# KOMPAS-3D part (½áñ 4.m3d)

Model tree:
1. Эскиз:1
2. Операция выдавливания:1
     Расстояние 1 = 20
3. Эскиз:2
4. Операция выдавливания:2
     Расстояние 1 = 400
5. Эскиз:3
6. Вырезать элемент выдавливания:1
     Расстояние 1 = 70
7. Эскиз:4
8. Вырезать элемент выдавливания:2
     Расстояние 1 = 2
9. Эскиз:5
10. Эскиз:11
11. Вырезать элемент выдавливания:7
     Расстояние 1 = 30
12. Операция выдавливания:3
     Расстояние 1 = 16.96
13. Эскиз:13
14. Вырезать элемент выдавливания:9
     Расстояние 1 = 70
15. Эскиз:14
16. Вырезать элемент выдавливания:10
     Расстояние 1 = 80
